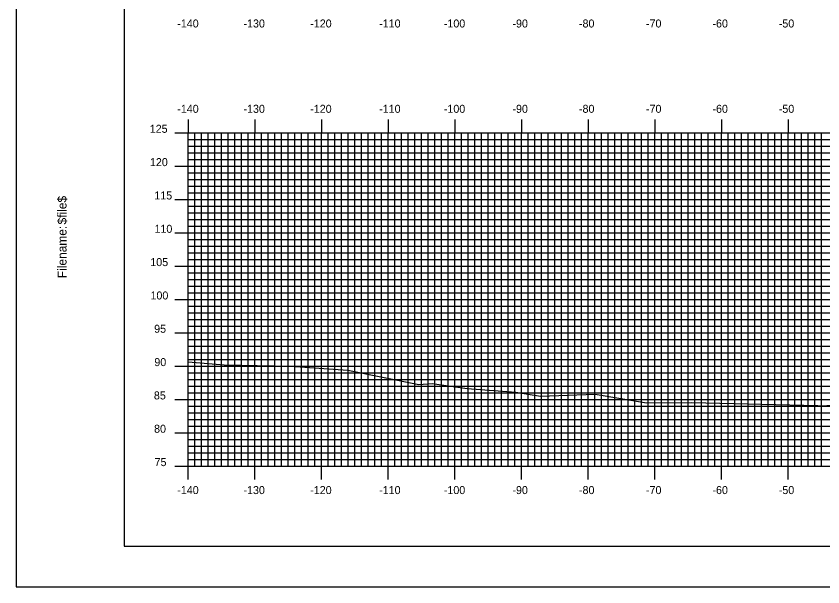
# Model space of a CAD drawing. Extents: x 856084 to 856427, y 364366 to 364586.
# Drawn here: x 856084 to 856205, y 364365.7 to 364451.3 of the extents above; entities that cross this region are included whole.
import ezdxf

# ---------------------------------------------------------------- set-up
doc = ezdxf.new("R2010")
doc.units = 0
for name, color, linetype in [('BORDER', 7, 'Continuous'), ('H_V ANNOTATION', 7, 'Continuous'), ('MAJOR', 7, 'Continuous'), ('MINOR', 7, 'Continuous'), ('PLOT BOUNDARY', 7, 'Continuous'), ('S_Roadway_Centerline', 7, 'Continuous')]:
    doc.layers.add(name, color=color, linetype=linetype)

msp = doc.modelspace()

# ---------------------------------------------------------------- linework, layer by layer
at = {"layer": 'BORDER'}
msp.add_lwpolyline([(856100.2, 364371.79), (856420.2, 364371.79), (856420.2, 364581.79), (856100.2, 364581.79)], close=True, dxfattribs=at)
at = {"layer": 'MAJOR'}
for p, q in [((856109.8, 364435.79), (856109.8, 364433.79)), ((856119.8, 364435.79), (856119.8, 364433.79)), ((856129.8, 364435.79), (856129.8, 364433.79)), ((856139.8, 364435.79), (856139.8, 364433.79)), ((856149.8, 364435.79), (856149.8, 364433.79)), ((856159.8, 364435.79), (856159.8, 364433.79)), ((856169.8, 364435.79), (856169.8, 364433.79)), ((856179.8, 364435.79), (856179.8, 364433.79)), ((856189.8, 364435.79), (856189.8, 364433.79)), ((856199.8, 364435.79), (856199.8, 364433.79)), ((856107.79, 364433.79), (856109.8, 364433.79)), ((856109.8, 364433.79), (856389.8, 364433.79)), ((856109.8, 364383.79), (856109.8, 364433.79)), ((856109.8, 364383.79), (856109.8, 364433.79)), ((856109.8, 364433.79), (856389.8, 364433.79)), ((856119.8, 364383.79), (856119.8, 364433.79)), ((856129.8, 364383.79), (856129.8, 364433.79)), ((856139.8, 364383.79), (856139.8, 364433.79)), ((856149.8, 364383.79), (856149.8, 364433.79)), ((856159.8, 364383.79), (856159.8, 364433.79)), ((856169.8, 364383.79), (856169.8, 364433.79)), ((856179.8, 364383.79), (856179.8, 364433.79)), ((856189.8, 364383.79), (856189.8, 364433.79)), ((856199.8, 364383.79), (856199.8, 364433.79)), ((856107.79, 364428.79), (856109.8, 364428.79)), ((856109.8, 364428.79), (856389.8, 364428.79)), ((856107.79, 364423.79), (856109.8, 364423.79)), ((856109.8, 364423.79), (856389.8, 364423.79)), ((856107.79, 364418.79), (856109.8, 364418.79)), ((856109.8, 364418.79), (856389.8, 364418.79)), ((856107.79, 364413.79), (856109.8, 364413.79)), ((856109.8, 364413.79), (856389.8, 364413.79)), ((856107.79, 364408.79), (856109.8, 364408.79)), ((856109.8, 364408.79), (856389.8, 364408.79)), ((856107.79, 364403.79), (856109.8, 364403.79)), ((856109.8, 364403.79), (856389.8, 364403.79)), ((856107.79, 364398.79), (856109.8, 364398.79)), ((856109.8, 364398.79), (856389.8, 364398.79)), ((856107.79, 364393.79), (856109.8, 364393.79)), ((856109.8, 364393.79), (856389.8, 364393.79)), ((856107.79, 364388.79), (856109.8, 364388.79)), ((856109.8, 364388.79), (856389.8, 364388.79)), ((856107.79, 364383.79), (856109.8, 364383.79)), ((856109.8, 364383.79), (856389.8, 364383.79)), ((856109.8, 364383.79), (856389.8, 364383.79)), ((856109.8, 364381.78), (856109.8, 364383.79)), ((856119.8, 364381.78), (856119.8, 364383.79)), ((856129.8, 364381.78), (856129.8, 364383.79)), ((856139.8, 364381.78), (856139.8, 364383.79)), ((856149.8, 364381.78), (856149.8, 364383.79)), ((856159.8, 364381.78), (856159.8, 364383.79)), ((856169.8, 364381.78), (856169.8, 364383.79)), ((856179.8, 364381.78), (856179.8, 364383.79)), ((856189.8, 364381.78), (856189.8, 364383.79)), ((856199.8, 364381.78), (856199.8, 364383.79))]:
    msp.add_line(p, q, dxfattribs=at)
at = {"layer": 'MINOR'}
for p, q in [((856110.8, 364383.79), (856110.8, 364433.79)), ((856111.8, 364383.79), (856111.8, 364433.79)), ((856112.8, 364383.79), (856112.8, 364433.79)), ((856113.8, 364383.79), (856113.8, 364433.79)), ((856114.8, 364383.79), (856114.8, 364433.79)), ((856115.8, 364383.79), (856115.8, 364433.79)), ((856116.8, 364383.79), (856116.8, 364433.79)), ((856117.8, 364383.79), (856117.8, 364433.79)), ((856118.8, 364383.79), (856118.8, 364433.79)), ((856120.8, 364383.79), (856120.8, 364433.79)), ((856121.8, 364383.79), (856121.8, 364433.79)), ((856122.8, 364383.79), (856122.8, 364433.79)), ((856123.8, 364383.79), (856123.8, 364433.79)), ((856124.8, 364383.79), (856124.8, 364433.79)), ((856125.8, 364383.79), (856125.8, 364433.79)), ((856126.8, 364383.79), (856126.8, 364433.79)), ((856127.8, 364383.79), (856127.8, 364433.79)), ((856128.8, 364383.79), (856128.8, 364433.79)), ((856130.8, 364383.79), (856130.8, 364433.79)), ((856131.8, 364383.79), (856131.8, 364433.79)), ((856132.8, 364383.79), (856132.8, 364433.79)), ((856133.8, 364383.79), (856133.8, 364433.79)), ((856134.8, 364383.79), (856134.8, 364433.79)), ((856135.8, 364383.79), (856135.8, 364433.79)), ((856136.8, 364383.79), (856136.8, 364433.79)), ((856137.8, 364383.79), (856137.8, 364433.79)), ((856138.8, 364383.79), (856138.8, 364433.79)), ((856140.8, 364383.79), (856140.8, 364433.79)), ((856141.8, 364383.79), (856141.8, 364433.79)), ((856142.8, 364383.79), (856142.8, 364433.79)), ((856143.8, 364383.79), (856143.8, 364433.79)), ((856144.8, 364383.79), (856144.8, 364433.79)), ((856145.8, 364383.79), (856145.8, 364433.79)), ((856146.8, 364383.79), (856146.8, 364433.79)), ((856147.8, 364383.79), (856147.8, 364433.79)), ((856148.8, 364383.79), (856148.8, 364433.79)), ((856150.8, 364383.79), (856150.8, 364433.79)), ((856151.8, 364383.79), (856151.8, 364433.79)), ((856152.8, 364383.79), (856152.8, 364433.79)), ((856153.8, 364383.79), (856153.8, 364433.79)), ((856154.8, 364383.79), (856154.8, 364433.79)), ((856155.8, 364383.79), (856155.8, 364433.79)), ((856156.8, 364383.79), (856156.8, 364433.79)), ((856157.8, 364383.79), (856157.8, 364433.79)), ((856158.8, 364383.79), (856158.8, 364433.79)), ((856160.8, 364383.79), (856160.8, 364433.79)), ((856161.8, 364383.79), (856161.8, 364433.79)), ((856162.8, 364383.79), (856162.8, 364433.79)), ((856163.8, 364383.79), (856163.8, 364433.79)), ((856164.8, 364383.79), (856164.8, 364433.79)), ((856165.8, 364383.79), (856165.8, 364433.79)), ((856166.8, 364383.79), (856166.8, 364433.79)), ((856167.8, 364383.79), (856167.8, 364433.79)), ((856168.8, 364383.79), (856168.8, 364433.79)), ((856170.8, 364383.79), (856170.8, 364433.79)), ((856171.8, 364383.79), (856171.8, 364433.79)), ((856172.8, 364383.79), (856172.8, 364433.79)), ((856173.8, 364383.79), (856173.8, 364433.79)), ((856174.8, 364383.79), (856174.8, 364433.79)), ((856175.8, 364383.79), (856175.8, 364433.79)), ((856176.8, 364383.79), (856176.8, 364433.79)), ((856177.8, 364383.79), (856177.8, 364433.79)), ((856178.8, 364383.79), (856178.8, 364433.79)), ((856180.8, 364383.79), (856180.8, 364433.79)), ((856181.8, 364383.79), (856181.8, 364433.79)), ((856182.8, 364383.79), (856182.8, 364433.79)), ((856183.8, 364383.79), (856183.8, 364433.79)), ((856184.8, 364383.79), (856184.8, 364433.79)), ((856185.8, 364383.79), (856185.8, 364433.79)), ((856186.8, 364383.79), (856186.8, 364433.79)), ((856187.8, 364383.79), (856187.8, 364433.79)), ((856188.8, 364383.79), (856188.8, 364433.79)), ((856190.8, 364383.79), (856190.8, 364433.79)), ((856191.8, 364383.79), (856191.8, 364433.79)), ((856192.8, 364383.79), (856192.8, 364433.79)), ((856193.8, 364383.79), (856193.8, 364433.79)), ((856194.8, 364383.79), (856194.8, 364433.79)), ((856195.8, 364383.79), (856195.8, 364433.79)), ((856196.8, 364383.79), (856196.8, 364433.79)), ((856197.8, 364383.79), (856197.8, 364433.79)), ((856198.8, 364383.79), (856198.8, 364433.79)), ((856200.8, 364383.79), (856200.8, 364433.79)), ((856201.8, 364383.79), (856201.8, 364433.79)), ((856202.8, 364383.79), (856202.8, 364433.79)), ((856203.8, 364383.79), (856203.8, 364433.79)), ((856204.8, 364383.79), (856204.8, 364433.79)), ((856109.8, 364432.79), (856389.8, 364432.79)), ((856109.8, 364432.79), (856111.8, 364432.79)), ((856109.8, 364431.79), (856389.8, 364431.79)), ((856109.8, 364431.79), (856111.8, 364431.79)), ((856109.8, 364430.79), (856389.8, 364430.79)), ((856109.8, 364430.79), (856111.8, 364430.79)), ((856109.8, 364429.79), (856389.8, 364429.79)), ((856109.8, 364429.79), (856111.8, 364429.79)), ((856109.8, 364427.79), (856389.8, 364427.79)), ((856109.8, 364427.79), (856111.8, 364427.79)), ((856109.8, 364426.79), (856389.8, 364426.79)), ((856109.8, 364426.79), (856111.8, 364426.79)), ((856109.8, 364425.79), (856389.8, 364425.79)), ((856109.8, 364425.79), (856111.8, 364425.79)), ((856109.8, 364424.79), (856389.8, 364424.79)), ((856109.8, 364424.79), (856111.8, 364424.79)), ((856109.8, 364422.79), (856389.8, 364422.79)), ((856109.8, 364422.79), (856111.8, 364422.79)), ((856109.8, 364421.79), (856389.8, 364421.79)), ((856109.8, 364421.79), (856111.8, 364421.79)), ((856109.8, 364420.79), (856389.8, 364420.79)), ((856109.8, 364420.79), (856111.8, 364420.79)), ((856109.8, 364419.79), (856389.8, 364419.79)), ((856109.8, 364419.79), (856111.8, 364419.79)), ((856109.8, 364417.79), (856389.8, 364417.79)), ((856109.8, 364417.79), (856111.8, 364417.79)), ((856109.8, 364416.79), (856389.8, 364416.79)), ((856109.8, 364416.79), (856111.8, 364416.79)), ((856109.8, 364415.79), (856389.8, 364415.79)), ((856109.8, 364415.79), (856111.8, 364415.79)), ((856109.8, 364414.79), (856389.8, 364414.79)), ((856109.8, 364414.79), (856111.8, 364414.79)), ((856109.8, 364412.79), (856389.8, 364412.79)), ((856109.8, 364412.79), (856111.8, 364412.79)), ((856109.8, 364411.79), (856389.8, 364411.79)), ((856109.8, 364411.79), (856111.8, 364411.79)), ((856109.8, 364410.79), (856389.8, 364410.79)), ((856109.8, 364410.79), (856111.8, 364410.79)), ((856109.8, 364409.79), (856389.8, 364409.79)), ((856109.8, 364409.79), (856111.8, 364409.79)), ((856109.8, 364407.79), (856389.8, 364407.79)), ((856109.8, 364407.79), (856111.8, 364407.79)), ((856109.8, 364406.79), (856389.8, 364406.79)), ((856109.8, 364406.79), (856111.8, 364406.79)), ((856109.8, 364405.79), (856389.8, 364405.79)), ((856109.8, 364405.79), (856111.8, 364405.79)), ((856109.8, 364404.79), (856389.8, 364404.79)), ((856109.8, 364404.79), (856111.8, 364404.79)), ((856109.8, 364402.79), (856389.8, 364402.79)), ((856109.8, 364402.79), (856111.8, 364402.79)), ((856109.8, 364401.79), (856389.8, 364401.79)), ((856109.8, 364401.79), (856111.8, 364401.79)), ((856109.8, 364400.79), (856389.8, 364400.79)), ((856109.8, 364400.79), (856111.8, 364400.79)), ((856109.8, 364399.79), (856389.8, 364399.79)), ((856109.8, 364399.79), (856111.8, 364399.79)), ((856109.8, 364397.79), (856389.8, 364397.79)), ((856109.8, 364397.79), (856111.8, 364397.79)), ((856109.8, 364396.79), (856389.8, 364396.79)), ((856109.8, 364396.79), (856111.8, 364396.79)), ((856109.8, 364395.79), (856389.8, 364395.79)), ((856109.8, 364395.79), (856111.8, 364395.79)), ((856109.8, 364394.79), (856389.8, 364394.79)), ((856109.8, 364394.79), (856111.8, 364394.79)), ((856109.8, 364392.79), (856389.8, 364392.79)), ((856109.8, 364392.79), (856111.8, 364392.79)), ((856109.8, 364391.79), (856389.8, 364391.79)), ((856109.8, 364391.79), (856111.8, 364391.79)), ((856109.8, 364390.79), (856389.8, 364390.79)), ((856109.8, 364390.79), (856111.8, 364390.79)), ((856109.8, 364389.79), (856389.8, 364389.79)), ((856109.8, 364389.79), (856111.8, 364389.79)), ((856109.8, 364387.79), (856389.8, 364387.79)), ((856109.8, 364387.79), (856111.8, 364387.79)), ((856109.8, 364386.79), (856389.8, 364386.79)), ((856109.8, 364386.79), (856111.8, 364386.79)), ((856109.8, 364385.79), (856389.8, 364385.79)), ((856109.8, 364385.79), (856111.8, 364385.79)), ((856109.8, 364384.79), (856389.8, 364384.79)), ((856109.8, 364384.79), (856111.8, 364384.79))]:
    msp.add_line(p, q, dxfattribs=at)
at = {"layer": 'PLOT BOUNDARY'}
msp.add_lwpolyline([(856084.01, 364365.67), (856424.01, 364365.67), (856424.01, 364585.67), (856084.01, 364585.67)], close=True, dxfattribs=at)
at = {"layer": 'S_Roadway_Centerline'}
msp.add_lwpolyline([(856109.8, 364399.43), (856115.2, 364398.98), (856125.16, 364398.8), (856133.78, 364398.17), (856144.41, 364396.05), (856146.43, 364396.17), (856151.67, 364395.44), (856158.96, 364394.86), (856162.68, 364394.27), (856170.87, 364394.59), (856178.56, 364393.27), (856185.37, 364393.34), (856204.28, 364392.9), (856204.92, 364392.84), (856217.77, 364393.71)], dxfattribs=at)

# ---------------------------------------------------------------- texts
at = {"layer": 'BORDER'}
for s, p in [('$file$', (856091.57, 364420.04)), ('Filename:', (856091.57, 364411.98))]:
    msp.add_text(s, height=1.339, rotation=90, dxfattribs=at).set_placement(p)
at = {"layer": 'H_V ANNOTATION'}
for s, p in [('-140', (856108.18, 364449.59)), ('-130', (856118.11, 364449.59)), ('-120', (856128.12, 364449.59)), ('-110', (856138.46, 364449.59)), ('-100', (856148.16, 364449.59)), ('-90', (856158.45, 364449.59)), ('-80', (856168.43, 364449.59)), ('-70', (856178.48, 364449.59)), ('-60', (856188.45, 364449.59)), ('-50', (856198.4, 364449.59)), ('-140', (856108.18, 364436.79)), ('-130', (856118.11, 364436.79)), ('-120', (856128.12, 364436.79)), ('-110', (856138.46, 364436.79)), ('-100', (856148.16, 364436.79)), ('-90', (856158.45, 364436.79)), ('-80', (856168.43, 364436.79)), ('-70', (856178.48, 364436.79)), ('-60', (856188.45, 364436.79)), ('-50', (856198.4, 364436.79)), ('125', (856104.05, 364433.79)), ('120', (856104.08, 364428.79)), ('115', (856104.73, 364423.79)), ('110', (856104.76, 364418.79)), ('105', (856104.13, 364413.79)), ('100', (856104.16, 364408.79)), ('95', (856104.71, 364403.79)), ('90', (856104.74, 364398.79)), ('85', (856104.67, 364393.79)), ('80', (856104.7, 364388.79)), ('75', (856104.77, 364383.79)), ('-140', (856108.18, 364379.59)), ('-130', (856118.11, 364379.59)), ('-120', (856128.12, 364379.59)), ('-110', (856138.46, 364379.59)), ('-100', (856148.16, 364379.59)), ('-90', (856158.45, 364379.59)), ('-80', (856168.43, 364379.59)), ('-70', (856178.48, 364379.59)), ('-60', (856188.45, 364379.59)), ('-50', (856198.4, 364379.59))]:
    msp.add_text(s, height=1.2, dxfattribs=at).set_placement(p)
at = {"layer": 'MAJOR'}
msp.add_text('-', height=0.012, dxfattribs=at).set_placement((856109.79, 364383.79))

doc.saveas('drawing.dxf')
